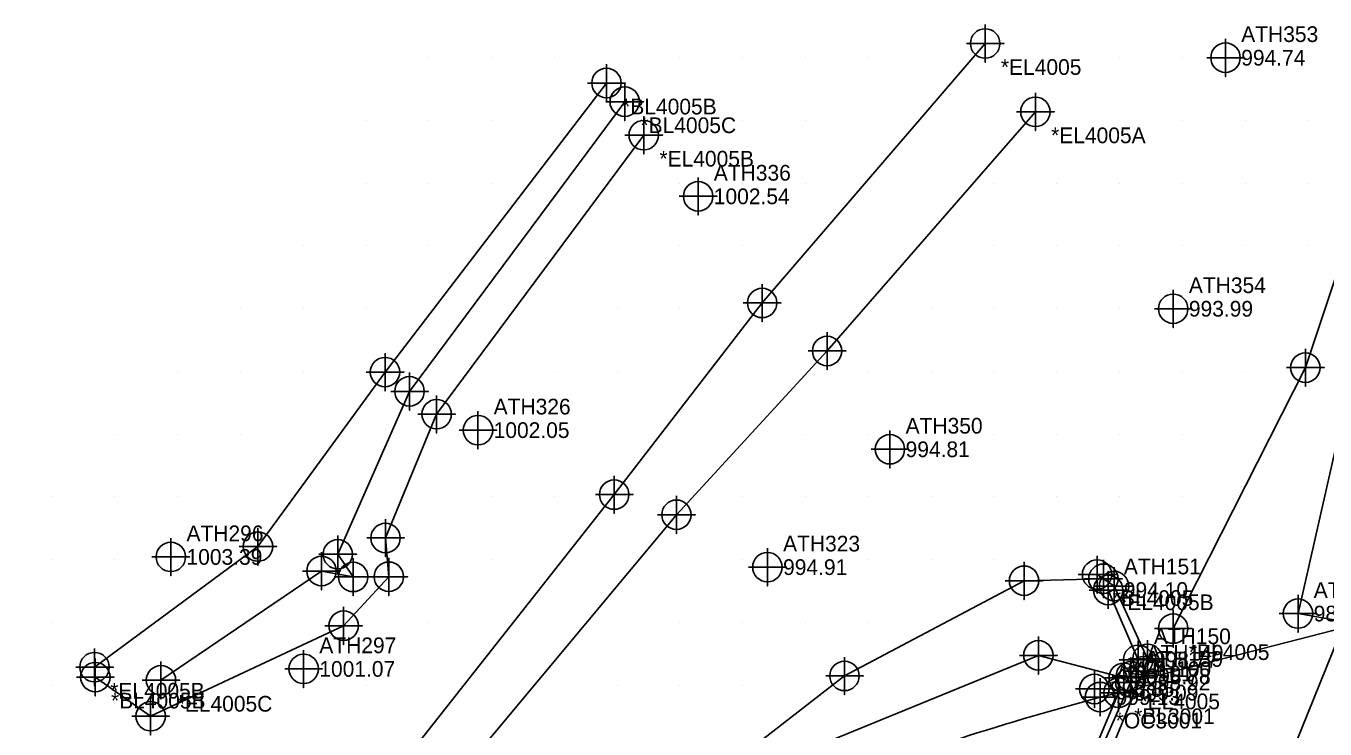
# Model space of a CAD drawing. Extents: x 1116680 to 1117499, y 661040 to 661703.
# Drawn here: x 1116855.8 to 1117062.7, y 661363 to 661475 of the extents above; entities that cross this region are included whole.
import ezdxf

# ---------------------------------------------------------------- set-up
doc = ezdxf.new("R2010")
doc.units = 0
for name, color, linetype in [('Exist DTM Breakline', 7, 'Continuous'), ('Exist DTM Breakline Cogo Comment', 7, 'Continuous'), ('Exist DTM Breakline Cogo Point CELL', 7, 'Continuous'), ('Exist DTM Drainline Cogo Elevation', 7, 'Continuous'), ('Exist DTM Drainline Cogo Number', 7, 'Continuous'), ('Exist DTM Drainline Cogo Point CELL', 7, 'Continuous'), ('Exist DTM QL2 LIDAR Elevation Point', 7, 'Continuous'), ('Exist DTM Regular Point CELL', 7, 'Continuous'), ('Exist DTM Regular Point Cogo Elevation', 7, 'Continuous'), ('Exist DTM Regular Point Cogo Number', 7, 'Continuous'), ('Exist Guardrail Cogo Elevation', 7, 'Continuous'), ('Exist Guardrail Cogo Point CELL', 7, 'Continuous'), ('Exist Hydro Stream or Body of Water', 7, 'Continuous'), ('Exist Roads EOP', 7, 'Continuous'), ('Exist Roads EOP Cogo Comment', 7, 'Continuous'), ('Exist Roads EOP Cogo Elevation', 7, 'Continuous'), ('Exist Roads EOP Cogo Number', 7, 'Continuous'), ('Exist Roads EOP Cogo Point CELL', 7, 'Continuous'), ('Exist Structure Major Bridge Seam Cogo Elevation', 7, 'Continuous'), ('Exist Structure Major Bridge Seam Cogo Number', 7, 'Continuous'), ('Exist Structure Major Bridge Seam Cogo Point CELL', 7, 'Continuous'), ('Exist Structure Major Bridge WW Cogo Elevation', 7, 'Continuous'), ('Exist Structure Major Bridge WW Cogo Number', 7, 'Continuous'), ('Exist Structure Major Bridge WW Cogo Point CELL', 7, 'Continuous'), ('Exist Structure Major Deck Tunnel Box Culvert', 7, 'Continuous')]:
    doc.layers.add(name, color=color, linetype=linetype)

msp = doc.modelspace()

# ---------------------------------------------------------------- linework, layer by layer
at = {"layer": 'Exist DTM Breakline'}
for points in [[(1117038.555, 661379.021), (1117059.605, 661420.588), (1117070.329, 661452.789), (1117088.813, 661488.846)], [(1116759.405, 661157.47), (1116807.255, 661219.832), (1116841.622, 661263.499), (1116875.544, 661313.217), (1116917.082, 661359.208), (1116949.523, 661400.365), (1116973.082, 661430.897), (1117008.611, 661472.228)], [(1116948.291, 661465.931), (1116913.02, 661419.88), (1116892.79, 661392.086), (1116866.757, 661372.871)], [(1116951.204, 661462.952), (1116916.926, 661416.811), (1116905.495, 661390.865), (1116907.94, 661387.249), (1116902.901, 661388.192), (1116877.334, 661370.792)], [(1116764.746, 661153.381), (1116812.662, 661214.66), (1116849.832, 661255.197), (1116886.132, 661304.973), (1116923.093, 661353.534), (1116959.436, 661397.157), (1116983.43, 661423.245), (1117016.608, 661461.344)], [(1116866.88, 661371.293), (1116875.69, 661365.058), (1116906.43, 661379.482), (1116913.621, 661387.282), (1116913.107, 661393.456), (1116921.238, 661413.169), (1116954.226, 661457.623)], [(1117026.431, 661387.63), (1117029.138, 661385.793), (1117034.453, 661374.2), (1117033.842, 661372.244), (1117022.619, 661345.013), (1117019.882, 661340.396), (1117009.557, 661330.24), (1117004.953, 661331.537)], [(1116777.711, 661140.704), (1116828.227, 661198.994), (1116863.907, 661242.056), (1116901.537, 661293.371), (1116942.909, 661337.866), (1116986.207, 661371.481), (1117014.804, 661386.644), (1117027.371, 661386.959)], [(1117031.808, 661371.415), (1117032.973, 661374.047), (1117028.193, 661385.164)], [(1116764.336, 661115.367), (1116780.79, 661135.76), (1116832.216, 661195.325), (1116868.599, 661238.611), (1116907.746, 661286.411), (1116949.649, 661334.962), (1116977.116, 661358.387), (1117017.083, 661374.758), (1117030.676, 661371.171)]]:
    msp.add_lwpolyline(points, dxfattribs=at)
at = {"layer": 'Exist DTM Breakline Cogo Point CELL'}
for points in [[(1117008.611, 661475.228), (1117008.611, 661469.228), (1117008.611, 661472.228), (1117011.611, 661472.228), (1117005.611, 661472.228)], [(1116948.291, 661468.931), (1116948.291, 661462.931), (1116948.291, 661465.931), (1116951.291, 661465.931), (1116945.291, 661465.931)], [(1116951.204, 661465.952), (1116951.204, 661459.952), (1116951.204, 661462.952), (1116954.204, 661462.952), (1116948.204, 661462.952)], [(1117016.608, 661464.344), (1117016.608, 661458.344), (1117016.608, 661461.344), (1117019.608, 661461.344), (1117013.608, 661461.344)], [(1116954.226, 661460.623), (1116954.226, 661454.623), (1116954.226, 661457.623), (1116957.226, 661457.623), (1116951.226, 661457.623)], [(1116973.082, 661433.897), (1116973.082, 661427.897), (1116973.082, 661430.897), (1116976.082, 661430.897), (1116970.082, 661430.897)], [(1116983.43, 661426.245), (1116983.43, 661420.245), (1116983.43, 661423.245), (1116986.43, 661423.245), (1116980.43, 661423.245)], [(1116913.02, 661422.88), (1116913.02, 661416.88), (1116913.02, 661419.88), (1116916.02, 661419.88), (1116910.02, 661419.88)], [(1117059.605, 661423.588), (1117059.605, 661417.588), (1117059.605, 661420.588), (1117062.605, 661420.588), (1117056.605, 661420.588)], [(1116916.926, 661419.811), (1116916.926, 661413.811), (1116916.926, 661416.811), (1116919.926, 661416.811), (1116913.926, 661416.811)], [(1116921.238, 661416.169), (1116921.238, 661410.169), (1116921.238, 661413.169), (1116924.238, 661413.169), (1116918.238, 661413.169)], [(1116949.523, 661403.365), (1116949.523, 661397.365), (1116949.523, 661400.365), (1116952.523, 661400.365), (1116946.523, 661400.365)], [(1116959.436, 661400.157), (1116959.436, 661394.157), (1116959.436, 661397.157), (1116962.436, 661397.157), (1116956.436, 661397.157)], [(1116913.107, 661396.456), (1116913.107, 661390.456), (1116913.107, 661393.456), (1116916.107, 661393.456), (1116910.107, 661393.456)], [(1116892.79, 661395.086), (1116892.79, 661389.086), (1116892.79, 661392.086), (1116895.79, 661392.086), (1116889.79, 661392.086)], [(1116905.495, 661393.865), (1116905.495, 661387.865), (1116905.495, 661390.865), (1116908.495, 661390.865), (1116902.495, 661390.865)], [(1116902.901, 661391.192), (1116902.901, 661385.192), (1116902.901, 661388.192), (1116905.901, 661388.192), (1116899.901, 661388.192)], [(1116907.94, 661390.249), (1116907.94, 661384.249), (1116907.94, 661387.249), (1116910.94, 661387.249), (1116904.94, 661387.249)], [(1116913.621, 661390.282), (1116913.621, 661384.282), (1116913.621, 661387.282), (1116916.621, 661387.282), (1116910.621, 661387.282)], [(1117014.804, 661389.644), (1117014.804, 661383.644), (1117014.804, 661386.644), (1117017.804, 661386.644), (1117011.804, 661386.644)], [(1117026.431, 661390.63), (1117026.431, 661384.63), (1117026.431, 661387.63), (1117029.431, 661387.63), (1117023.431, 661387.63)], [(1117027.44, 661389.961), (1117027.44, 661383.961), (1117027.44, 661386.961), (1117030.44, 661386.961), (1117024.44, 661386.961)], [(1117029.138, 661388.793), (1117029.138, 661382.793), (1117029.138, 661385.793), (1117032.138, 661385.793), (1117026.138, 661385.793)], [(1116906.43, 661382.482), (1116906.43, 661376.482), (1116906.43, 661379.482), (1116909.43, 661379.482), (1116903.43, 661379.482)], [(1117038.555, 661382.021), (1117038.555, 661376.021), (1117038.555, 661379.021), (1117041.555, 661379.021), (1117035.555, 661379.021)], [(1117017.083, 661377.758), (1117017.083, 661371.758), (1117017.083, 661374.758), (1117020.083, 661374.758), (1117014.083, 661374.758)], [(1117034.453, 661377.2), (1117034.453, 661371.2), (1117034.453, 661374.2), (1117037.453, 661374.2), (1117031.453, 661374.2)], [(1116866.757, 661375.871), (1116866.757, 661369.871), (1116866.757, 661372.871), (1116869.757, 661372.871), (1116863.757, 661372.871)], [(1117033.842, 661375.244), (1117033.842, 661369.244), (1117033.842, 661372.244), (1117036.842, 661372.244), (1117030.842, 661372.244)], [(1116866.88, 661374.293), (1116866.88, 661368.293), (1116866.88, 661371.293), (1116869.88, 661371.293), (1116863.88, 661371.293)], [(1116877.334, 661373.792), (1116877.334, 661367.792), (1116877.334, 661370.792), (1116880.334, 661370.792), (1116874.334, 661370.792)], [(1116986.207, 661374.481), (1116986.207, 661368.481), (1116986.207, 661371.481), (1116989.207, 661371.481), (1116983.207, 661371.481)], [(1117030.676, 661374.171), (1117030.676, 661368.171), (1117030.676, 661371.171), (1117033.676, 661371.171), (1117027.676, 661371.171)], [(1116875.69, 661368.058), (1116875.69, 661362.058), (1116875.69, 661365.058), (1116878.69, 661365.058), (1116872.69, 661365.058)]]:
    msp.add_lwpolyline(points, dxfattribs=at)
for centre in [(1117008.611, 661472.228), (1116948.291, 661465.931), (1116951.204, 661462.952), (1117016.608, 661461.344), (1116954.226, 661457.623), (1116973.082, 661430.897), (1116983.43, 661423.245), (1117059.605, 661420.588), (1116913.02, 661419.88), (1116916.926, 661416.811), (1116921.238, 661413.169), (1116949.523, 661400.365), (1116959.436, 661397.157), (1116913.107, 661393.456), (1116892.79, 661392.086), (1116905.495, 661390.865), (1116902.901, 661388.192), (1116907.94, 661387.249), (1116913.621, 661387.282), (1117026.431, 661387.63), (1117014.804, 661386.644), (1117027.44, 661386.961), (1117029.138, 661385.793), (1116906.43, 661379.482), (1117038.555, 661379.021), (1116866.757, 661372.871), (1117017.083, 661374.758), (1117034.453, 661374.2), (1116866.88, 661371.293), (1116877.334, 661370.792), (1116986.207, 661371.481), (1117030.676, 661371.171), (1117033.842, 661372.244), (1116875.69, 661365.058)]:
    msp.add_circle(centre, 2.344, dxfattribs=at)
at = {"layer": 'Exist DTM Drainline Cogo Point CELL'}
msp.add_lwpolyline([(1117058.435, 661384.413), (1117058.435, 661378.413), (1117058.435, 661381.413), (1117061.435, 661381.413), (1117055.435, 661381.413)], dxfattribs=at)
msp.add_circle((1117058.435, 661381.413), 2.344, dxfattribs=at)
at = {"layer": 'Exist DTM QL2 LIDAR Elevation Point'}
for p, q in [((1116920, 661470), (1116920, 661470)), ((1116930, 661470), (1116930, 661470)), ((1116940, 661470), (1116940, 661470)), ((1116960, 661470), (1116960, 661470)), ((1116970, 661470), (1116970, 661470)), ((1116980, 661470), (1116980, 661470)), ((1116990, 661470), (1116990, 661470)), ((1117020, 661470), (1117020, 661470)), ((1117030, 661470), (1117030, 661470)), ((1117040, 661470), (1117040, 661470)), ((1117050, 661470), (1117050, 661470)), ((1117060, 661470), (1117060, 661470)), ((1116910, 661460), (1116910, 661460)), ((1116920, 661460), (1116920, 661460)), ((1116930, 661460), (1116930, 661460)), ((1116970, 661460), (1116970, 661460)), ((1116980, 661460), (1116980, 661460)), ((1117030, 661460), (1117030, 661460)), ((1117040, 661460), (1117040, 661460)), ((1117050, 661460), (1117050, 661460)), ((1117060, 661460), (1117060, 661460)), ((1116910, 661450), (1116910, 661450)), ((1116920, 661450), (1116920, 661450)), ((1116930, 661450), (1116930, 661450)), ((1116960, 661450), (1116960, 661450)), ((1116970, 661450), (1116970, 661450)), ((1116980, 661450), (1116980, 661450)), ((1117010, 661450), (1117010, 661450)), ((1117020, 661450), (1117020, 661450)), ((1117030, 661450), (1117030, 661450)), ((1117040, 661450), (1117040, 661450)), ((1117050, 661450), (1117050, 661450)), ((1117060, 661450), (1117060, 661450)), ((1116900, 661440), (1116900, 661440)), ((1116910, 661440), (1116910, 661440)), ((1116920, 661440), (1116920, 661440)), ((1116960, 661440), (1116960, 661440)), ((1116970, 661440), (1116970, 661440)), ((1117010, 661440), (1117010, 661440)), ((1117020, 661440), (1117020, 661440)), ((1117030, 661440), (1117030, 661440)), ((1117040, 661440), (1117040, 661440)), ((1117050, 661440), (1117050, 661440)), ((1117060, 661440), (1117060, 661440)), ((1116890, 661430), (1116890, 661430)), ((1116900, 661430), (1116900, 661430)), ((1116910, 661430), (1116910, 661430)), ((1116950, 661430), (1116950, 661430)), ((1116960, 661430), (1116960, 661430)), ((1117000, 661430), (1117000, 661430)), ((1117010, 661430), (1117010, 661430)), ((1117020, 661430), (1117020, 661430)), ((1117030, 661430), (1117030, 661430)), ((1117040, 661430), (1117040, 661430)), ((1117050, 661430), (1117050, 661430)), ((1116880, 661420), (1116880, 661420)), ((1116890, 661420), (1116890, 661420)), ((1116900, 661420), (1116900, 661420)), ((1116940, 661420), (1116940, 661420)), ((1116950, 661420), (1116950, 661420)), ((1116990, 661420), (1116990, 661420)), ((1117000, 661420), (1117000, 661420)), ((1117010, 661420), (1117010, 661420)), ((1117020, 661420), (1117020, 661420)), ((1117030, 661420), (1117030, 661420)), ((1117040, 661420), (1117040, 661420)), ((1117050, 661420), (1117050, 661420)), ((1116870, 661410), (1116870, 661410)), ((1116880, 661410), (1116880, 661410)), ((1116890, 661410), (1116890, 661410)), ((1116940, 661410), (1116940, 661410)), ((1116980, 661410), (1116980, 661410)), ((1116990, 661410), (1116990, 661410)), ((1117000, 661410), (1117000, 661410)), ((1117010, 661410), (1117010, 661410)), ((1117020, 661410), (1117020, 661410)), ((1117030, 661410), (1117030, 661410)), ((1117040, 661410), (1117040, 661410)), ((1116860, 661400), (1116860, 661400)), ((1116870, 661400), (1116870, 661400)), ((1116880, 661400), (1116880, 661400)), ((1116930, 661400), (1116930, 661400)), ((1116940, 661400), (1116940, 661400)), ((1116970, 661400), (1116970, 661400)), ((1116980, 661400), (1116980, 661400)), ((1116990, 661400), (1116990, 661400)), ((1117000, 661400), (1117000, 661400)), ((1117010, 661400), (1117010, 661400)), ((1117020, 661400), (1117020, 661400)), ((1117030, 661400), (1117030, 661400)), ((1117040, 661400), (1117040, 661400)), ((1116860, 661390), (1116860, 661390)), ((1116870, 661390), (1116870, 661390)), ((1116930, 661390), (1116930, 661390)), ((1116970, 661390), (1116970, 661390)), ((1116980, 661390), (1116980, 661390)), ((1116990, 661390), (1116990, 661390)), ((1117000, 661390), (1117000, 661390)), ((1117010, 661390), (1117010, 661390)), ((1116860, 661380), (1116860, 661380)), ((1116920, 661380), (1116920, 661380)), ((1116960, 661380), (1116960, 661380)), ((1116970, 661380), (1116970, 661380)), ((1116980, 661380), (1116980, 661380)), ((1116990, 661380), (1116990, 661380)), ((1116860, 661370), (1116860, 661370)), ((1116910, 661370), (1116910, 661370)), ((1116950, 661370), (1116950, 661370)), ((1116960, 661370), (1116960, 661370)), ((1116970, 661370), (1116970, 661370))]:
    msp.add_line(p, q, dxfattribs=at)
at = {"layer": 'Exist DTM Regular Point CELL'}
for points in [[(1117046.889, 661472.962), (1117046.889, 661466.962), (1117046.889, 661469.962), (1117049.889, 661469.962), (1117043.889, 661469.962)], [(1116962.889, 661450.88), (1116962.889, 661444.88), (1116962.889, 661447.88), (1116965.889, 661447.88), (1116959.889, 661447.88)], [(1117038.551, 661432.967), (1117038.551, 661426.967), (1117038.551, 661429.967), (1117041.551, 661429.967), (1117035.551, 661429.967)], [(1116927.825, 661413.634), (1116927.825, 661407.634), (1116927.825, 661410.634), (1116930.825, 661410.634), (1116924.825, 661410.634)], [(1116993.435, 661410.584), (1116993.435, 661404.584), (1116993.435, 661407.584), (1116996.435, 661407.584), (1116990.435, 661407.584)], [(1116878.906, 661393.441), (1116878.906, 661387.441), (1116878.906, 661390.441), (1116881.906, 661390.441), (1116875.906, 661390.441)], [(1116973.923, 661391.811), (1116973.923, 661385.811), (1116973.923, 661388.811), (1116976.923, 661388.811), (1116970.923, 661388.811)], [(1116900.06, 661375.603), (1116900.06, 661369.603), (1116900.06, 661372.603), (1116903.06, 661372.603), (1116897.06, 661372.603)]]:
    msp.add_lwpolyline(points, dxfattribs=at)
for centre in [(1117046.889, 661469.962), (1116962.889, 661447.88), (1117038.551, 661429.967), (1116927.825, 661410.634), (1116993.435, 661407.584), (1116878.906, 661390.441), (1116973.923, 661388.811), (1116900.06, 661372.603)]:
    msp.add_circle(centre, 2.344, dxfattribs=at)
at = {"layer": 'Exist Guardrail Cogo Point CELL'}
msp.add_lwpolyline([(1117026, 661372.4), (1117026, 661366.4), (1117026, 661369.4), (1117029, 661369.4), (1117023, 661369.4)], dxfattribs=at)
msp.add_circle((1117026, 661369.4), 2.344, dxfattribs=at)
at = {"layer": 'Exist Hydro Stream or Body of Water'}
msp.add_lwpolyline([(1116885.259, 661065.084), (1116909.522, 661128.826), (1116941.429, 661187.261), (1116973.299, 661231.015), (1117008.806, 661288.675), (1117028.625, 661329.39), (1117037.259, 661346.044), (1117054.084, 661350.959), (1117065.864, 661380.085), (1117058.435, 661381.413), (1117066.561, 661417.266), (1117077.352, 661449.252), (1117098.924, 661488.98)], dxfattribs=at)
at = {"layer": 'Exist Roads EOP'}
msp.add_line((1117029.838, 661368.807), (1117026.904, 661368.114), dxfattribs=at)
msp.add_lwpolyline([(1117021.234, 661347.049), (1117025.187, 661357.713), (1117029.838, 661368.807)], dxfattribs=at)
msp.add_spline([(1117026.904, 661368.114), (1116980.178, 661351.152), (1116952.946, 661330.95), (1116925.984, 661301.817)], degree=3, dxfattribs=at)
at = {"layer": 'Exist Roads EOP Cogo Point CELL'}
for points in [[(1117026.904, 661371.114), (1117026.904, 661365.114), (1117026.904, 661368.114), (1117029.904, 661368.114), (1117023.904, 661368.114)], [(1117029.838, 661371.807), (1117029.838, 661365.807), (1117029.838, 661368.807), (1117032.838, 661368.807), (1117026.838, 661368.807)]]:
    msp.add_lwpolyline(points, dxfattribs=at)
for centre in [(1117029.838, 661368.807), (1117026.904, 661368.114)]:
    msp.add_circle(centre, 2.344, dxfattribs=at)
at = {"layer": 'Exist Structure Major Bridge Seam Cogo Point CELL'}
msp.add_lwpolyline([(1117028.737, 661370.434), (1117034.737, 661370.434), (1117031.737, 661370.434), (1117031.737, 661373.434), (1117031.737, 661367.434)], dxfattribs=at)
msp.add_circle((1117031.737, 661370.434), 2.344, dxfattribs=at)
at = {"layer": 'Exist Structure Major Bridge WW Cogo Point CELL'}
for points in [[(1117025.193, 661385.164), (1117031.193, 661385.164), (1117028.193, 661385.164), (1117028.193, 661388.164), (1117028.193, 661382.164)], [(1117029.973, 661374.047), (1117035.973, 661374.047), (1117032.973, 661374.047), (1117032.973, 661377.047), (1117032.973, 661371.047)], [(1117028.808, 661371.415), (1117034.808, 661371.415), (1117031.808, 661371.415), (1117031.808, 661374.415), (1117031.808, 661368.415)]]:
    msp.add_lwpolyline(points, dxfattribs=at)
for centre in [(1117028.193, 661385.164), (1117032.973, 661374.047), (1117031.808, 661371.415)]:
    msp.add_circle(centre, 2.344, dxfattribs=at)
at = {"layer": 'Exist Structure Major Deck Tunnel Box Culvert'}
msp.add_lwpolyline([(1117031.737, 661370.434), (1117096.438, 661387.065), (1117083.188, 661361.127), (1117020.55, 661345.005), (1117031.737, 661370.434)], dxfattribs=at)

# ---------------------------------------------------------------- texts
at = {"layer": 'Exist DTM Breakline Cogo Comment'}
for s, p in [('*EL4005', (1117011.111, 661467.228)), ('*BL4005B', (1116950.791, 661460.931)), ('*BL4005C', (1116953.704, 661457.952)), ('*EL4005A', (1117019.108, 661456.344)), ('*EL4005B', (1116956.726, 661452.623)), ('*BL4005', (1117028.931, 661382.63)), ('*EL4005B', (1117029.94, 661381.961)), ('*BL4005', (1117041.055, 661374.021)), ('*EL4005B', (1116869.257, 661367.871)), ('*BL4005B', (1116869.38, 661366.293)), ('*EL4005C', (1116879.834, 661365.792)), ('*EL4005', (1117033.176, 661366.171))]:
    msp.add_text(s, height=2.5, dxfattribs=at).set_placement(p)
at = {"layer": 'Exist DTM Drainline Cogo Elevation'}
msp.add_text('988.08', height=2.5, dxfattribs=at).set_placement((1117060.935, 661380.163))
at = {"layer": 'Exist DTM Drainline Cogo Number'}
msp.add_text('ATH319', height=2.5, dxfattribs=at).set_placement((1117060.935, 661383.913))
at = {"layer": 'Exist DTM Regular Point Cogo Elevation'}
for s, p in [('994.74', (1117049.389, 661468.712)), ('1002.54', (1116965.389, 661446.63)), ('993.99', (1117041.051, 661428.717)), ('1002.05', (1116930.325, 661409.384)), ('994.81', (1116995.935, 661406.334)), ('1003.39', (1116881.406, 661389.191)), ('994.91', (1116976.423, 661387.561)), ('1001.07', (1116902.56, 661371.353))]:
    msp.add_text(s, height=2.5, dxfattribs=at).set_placement(p)
at = {"layer": 'Exist DTM Regular Point Cogo Number'}
for s, p in [('ATH353', (1117049.389, 661472.462)), ('ATH336', (1116965.389, 661450.38)), ('ATH354', (1117041.051, 661432.467)), ('ATH326', (1116930.325, 661413.134)), ('ATH350', (1116995.935, 661410.084)), ('ATH296', (1116881.406, 661392.941)), ('ATH323', (1116976.423, 661391.311)), ('ATH297', (1116902.56, 661375.103))]:
    msp.add_text(s, height=2.5, dxfattribs=at).set_placement(p)
at = {"layer": 'Exist Guardrail Cogo Elevation'}
msp.add_text('998.85', height=2.5, dxfattribs=at).set_placement((1117028.5, 661368.15))
at = {"layer": 'Exist Roads EOP Cogo Comment'}
for s, p in [('*OC3001', (1117029.404, 661363.114)), ('*BL3001', (1117032.338, 661363.807))]:
    msp.add_text(s, height=2.5, dxfattribs=at).set_placement(p)
at = {"layer": 'Exist Roads EOP Cogo Elevation'}
for s, p in [('999.13', (1117029.404, 661366.864)), ('999.09', (1117032.338, 661367.557))]:
    msp.add_text(s, height=2.5, dxfattribs=at).set_placement(p)
at = {"layer": 'Exist Roads EOP Cogo Number'}
for s, p in [('ATH101', (1117029.404, 661370.614)), ('ATH100', (1117032.338, 661371.307))]:
    msp.add_text(s, height=2.5, dxfattribs=at).set_placement(p)
at = {"layer": 'Exist Structure Major Bridge Seam Cogo Elevation'}
msp.add_text('998.92', height=2.5, dxfattribs=at).set_placement((1117034.237, 661369.184))
at = {"layer": 'Exist Structure Major Bridge Seam Cogo Number'}
msp.add_text('ATH139', height=2.5, dxfattribs=at).set_placement((1117034.237, 661372.934))
at = {"layer": 'Exist Structure Major Bridge WW Cogo Elevation'}
for s, p in [('994.10', (1117030.693, 661383.914)), ('998.77', (1117035.473, 661372.797)), ('998.78', (1117034.308, 661370.165))]:
    msp.add_text(s, height=2.5, dxfattribs=at).set_placement(p)
at = {"layer": 'Exist Structure Major Bridge WW Cogo Number'}
for s, p in [('ATH151', (1117030.693, 661387.664)), ('ATH150', (1117035.473, 661376.547)), ('ATH149', (1117034.308, 661373.915))]:
    msp.add_text(s, height=2.5, dxfattribs=at).set_placement(p)

doc.saveas('drawing.dxf')
